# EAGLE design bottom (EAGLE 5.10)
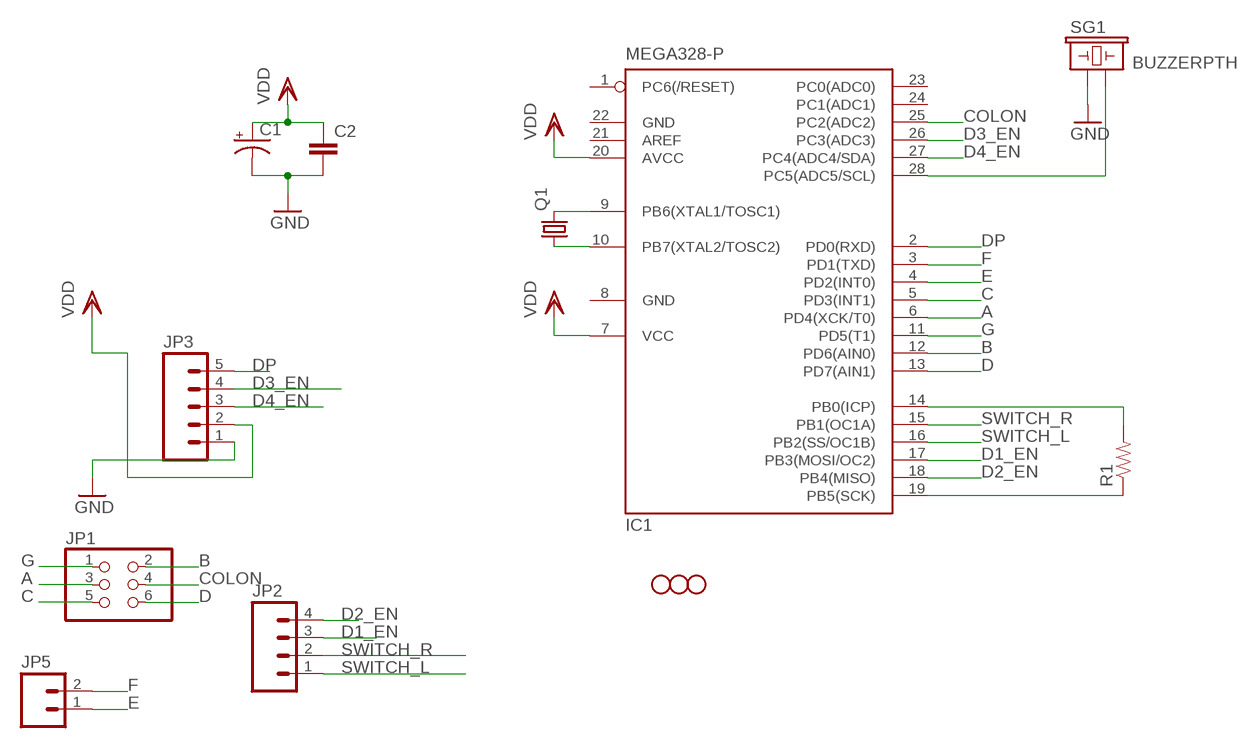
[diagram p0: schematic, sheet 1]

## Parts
C1  CAP_POLPTH2  [CPOL-RADIAL-10UF-25V]
C2  CAPPTH  [CAP-PTH-SMALL]
IC1  MEGA328-P  MEGA8-P  [DIL28-3]
JP1  PINHD-2X3  [2X03]
JP2  M04PTH  [1X04]
JP3  M05PTH  [1X05]
JP4  STAND-OFF  [STAND-OFF]
JP5  M02PTH  [1X02]
JP6  STAND-OFF  [STAND-OFF]
JP7  STAND-OFF  [STAND-OFF]
Q1  CRYSTALTC26H  [TC26H]
R1  RESISTORPTH-1/6W  [1/6W-RES]
SG1  BUZZERPTH  [BUZZER-12MM]

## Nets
A: IC1.6(PD4(XCK/T0)) JP1.3
B: IC1.12(PD6(AIN0)) JP1.2
C: IC1.5(PD3(INT1)) JP1.5
CAP_REC: IC1.19(PB5(SCK)) R1.1
CAP_TRANS: IC1.14(PB0(ICP)) R1.2
COLON: IC1.25(PC2(ADC2)) JP1.4
D: IC1.13(PD7(AIN1)) JP1.6
D1_EN: IC1.17(PB3(MOSI/OC2)) JP2.3
D2_EN: IC1.18(PB4(MISO)) JP2.4
D3_EN: IC1.26(PC3(ADC3)) JP3.4
D4_EN: IC1.27(PC4(ADC4/SDA)) JP3.3
DP: IC1.2(PD0(RXD)) JP3.5
E: IC1.4(PD2(INT0)) JP5.1
F: IC1.3(PD1(TXD)) JP5.2
G: IC1.11(PD5(T1)) JP1.1
GND: C1.2(-) C2.2 JP3.1 SG1.+
N$1: IC1.9(PB6(XTAL1/TOSC1)) Q1.2
N$2: IC1.10(PB7(XTAL2/TOSC2)) Q1.1
N$4: IC1.28(PC5(ADC5/SCL)) SG1.-
SWITCH_L: IC1.16(PB2(SS/OC1B)) JP2.1
SWITCH_R: IC1.15(PB1(OC1A)) JP2.2
VDD: C1.1(+) C2.1 IC1.7(VCC) IC1.20(AVCC) JP3.2
Unconnected: IC1.1(PC6(/RESET)) IC1.21(AREF) IC1.23(PC0(ADC0)) IC1.24(PC1(ADC1))

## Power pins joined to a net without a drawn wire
GND: IC1.8(GND) IC1.22(GND)

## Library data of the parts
C1 = SparkFun:CAP_POL: Capacitor Polarized
C2 = SparkFun:CAP: Capacitor
IC1 = atmel:MEGA8-P: MICROCONTROLLER 8 Kbytes FLASH, 1 kbytes SRAM, 512 bytes EEPROM, USART, 4-channel 10 bit ADC, 2-channel 8 bit ADC Pin compatible with Atmega48, ATMega88, ATMega168 Source: avr.lbr
JP1 = SparkFun:PINHD-2X3: PIN HEADER
JP2 = SparkFun:M04: Header 4 Standard 4-pin 0.1" header. Use with straight break away headers (SKU : PRT-00116), right angle break away headers (PRT-00553), swiss pins (PRT-00743), machine pins (PRT-00117), and female headers (PRT-00115). Molex polarized connector foot print use with SKU : PRT-08231 with associated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
JP3 = SparkFun:M05: Header 5 Standard 5-pin 0.1" header. Use with straight break away headers (SKU : PRT-00116), right angle break away headers (PRT-00553), swiss pins (PRT-00743), machine pins (PRT-00117), and female headers (PRT-00115). Molex polarized connector foot print use with SKU : PRT-08230 with associated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
JP4 JP6 JP7 = SparkFun:STAND-OFF: Stand Off
JP5 = SparkFun:M02: Header 2
Q1 = SparkFun:CRYSTAL: Crystals
R1 = SparkFun:RESISTOR: Resistor
SG1 = SparkFun:BUZZER: Buzzer 12mm

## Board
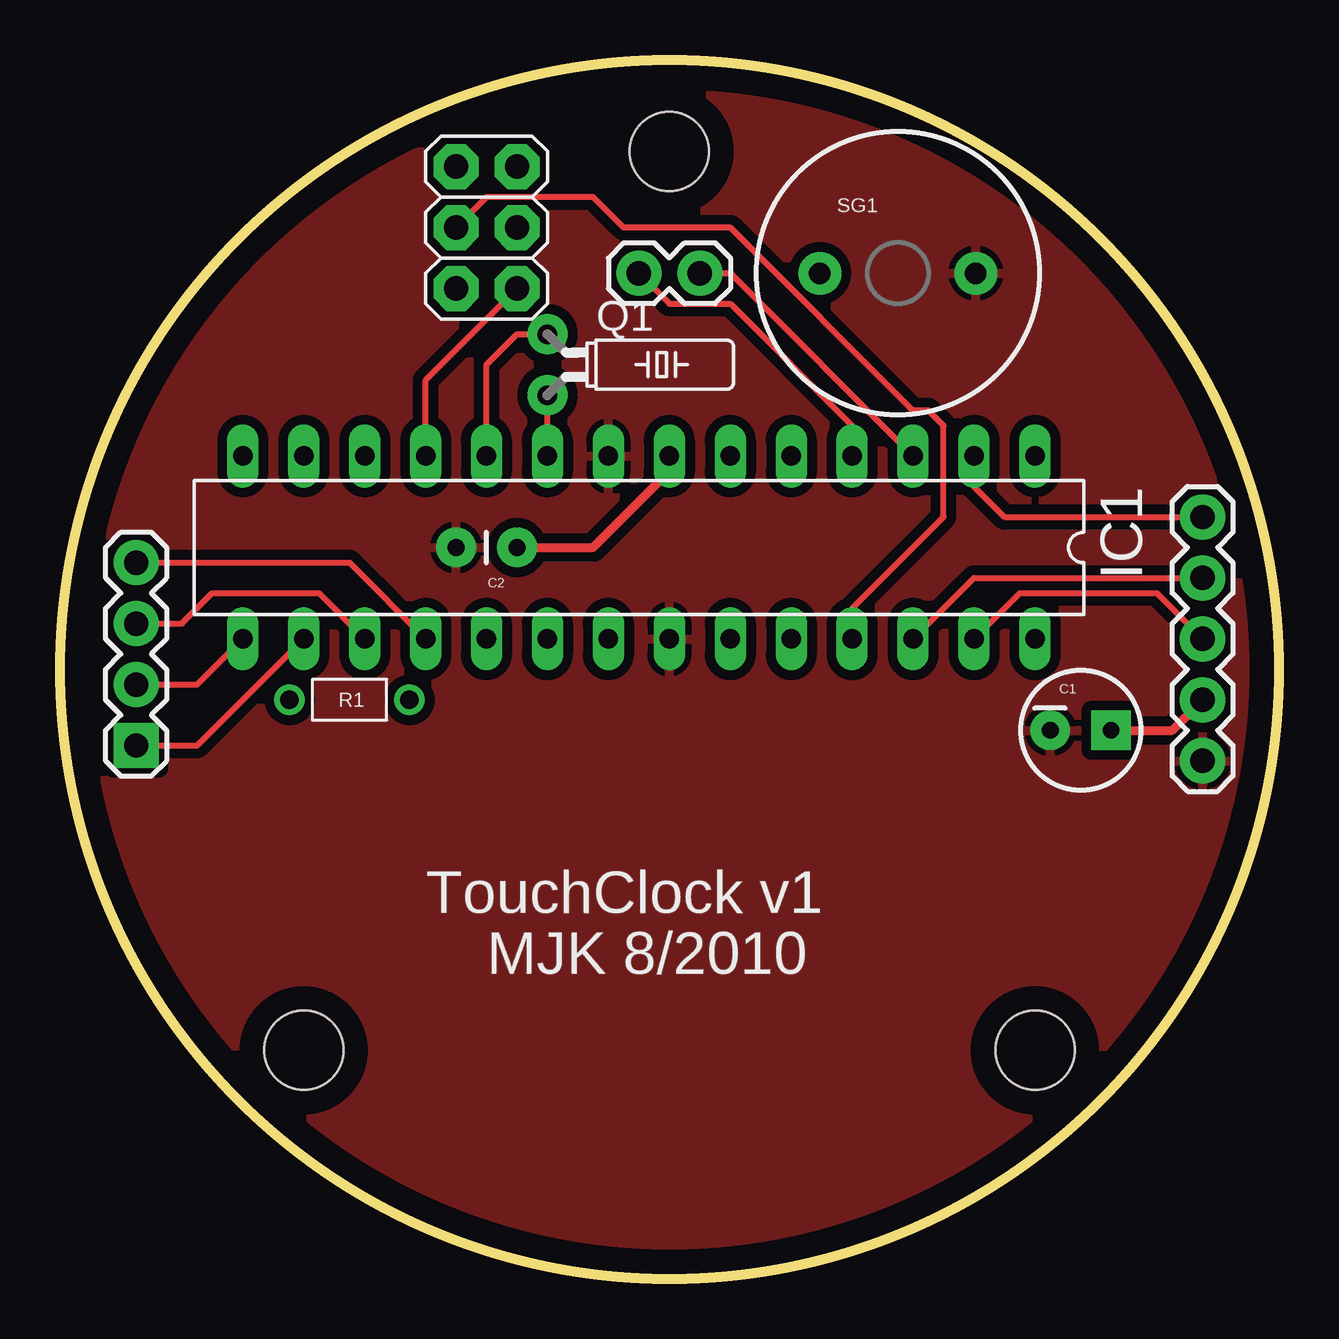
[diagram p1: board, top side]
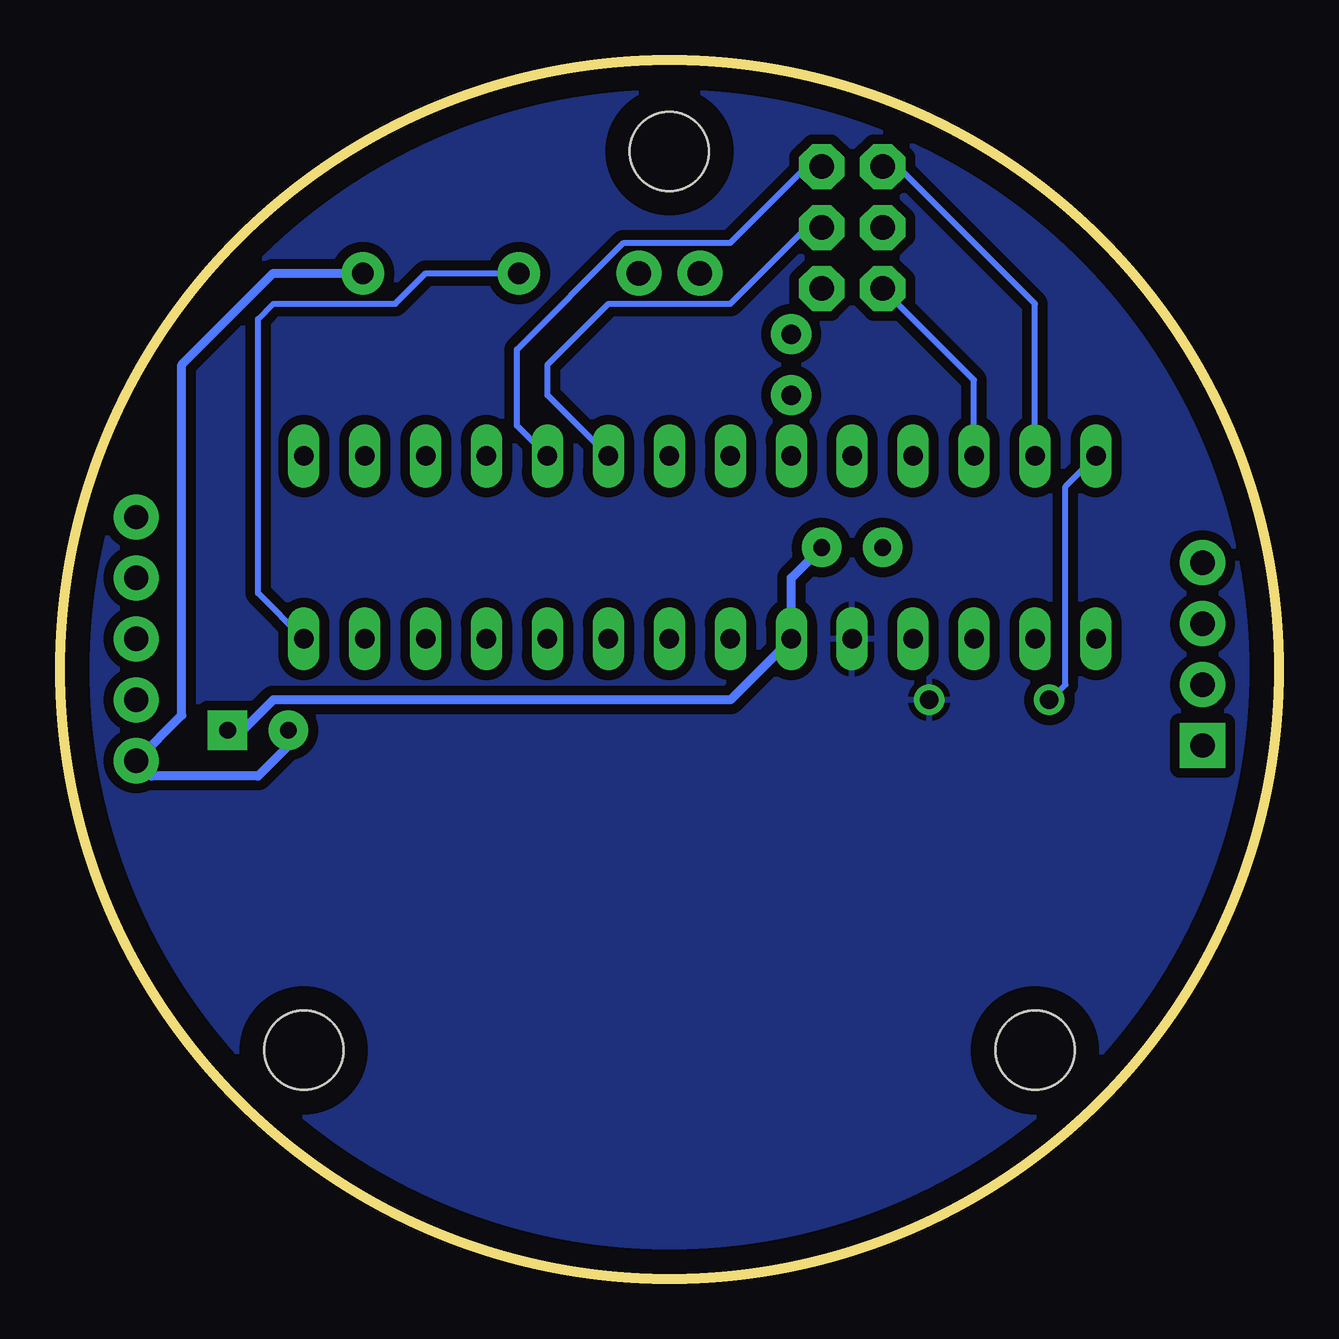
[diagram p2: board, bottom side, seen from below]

Size 50.8 x 50.8 mm. Coordinates in mm from the lower left corner, seen from the top.
Outline: circle at 25.4,25.4 radius 25.4
Copper layers (1*16): Top 0.035mm / dielectric 1.5mm / Bottom 0.035mm
Design rules "default": minimum track width 10mil, minimum drill 24mil, track to track 8mil, track to pad 8mil, pad to pad 8mil, via to via 8mil, smd to smd 8mil, copper to edge 40mil, drill to drill 8mil, minimum pad ring 10mil, minimum via ring 8mil, stop-mask expansion 4mil, vias tented up to drill 0mil, thermal gap 10mil

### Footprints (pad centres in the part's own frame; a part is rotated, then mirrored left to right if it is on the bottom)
CPOL-RADIAL-10UF-25V = drill 0.7 pad 1.651 square: 1 1.27,0 | drill 0.7 pad 1.651 round: 2 -1.27,0
CAP-PTH-SMALL = drill 0.7 pad 1.651 round: 1 0,0; 2 2.54,0
DIL28-3 = drill 0.813 long: 1 -16.51,-3.81; 2 -13.97,-3.81; 3 -11.43,-3.81; 4 -8.89,-3.81; 5 -6.35,-3.81; 6 -3.81,-3.81; 7 -1.27,-3.81; 8 1.27,-3.81; 9 3.81,-3.81; 10 6.35,-3.81; 11 8.89,-3.81; 12 11.43,-3.81; 13 13.97,-3.81; 14 16.51,-3.81; 15 16.51,3.81; 16 13.97,3.81; 17 11.43,3.81; 18 8.89,3.81; 19 6.35,3.81; 20 3.81,3.81; 21 1.27,3.81; 22 -1.27,3.81; 23 -3.81,3.81; 24 -6.35,3.81; 25 -8.89,3.81; 26 -11.43,3.81; 27 -13.97,3.81; 28 -16.51,3.81
2X03 = drill 1.016 pad 1.88 octagon: 1 -2.54,-1.27; 2 -2.54,1.27; 3 0,-1.27; 4 0,1.27; 5 2.54,-1.27; 6 2.54,1.27
1X04 = drill 1.016 pad 1.88 square: 1 0,0 | drill 1.016 pad 1.88 round: 2 2.54,0; 3 5.08,0; 4 7.62,0
1X05 = drill 1.016 pad 1.88 round: 1 0,0; 2 2.54,0; 3 5.08,0; 4 7.62,0; 5 10.16,0
STAND-OFF = hole 3.302: 0,0
1X02 = drill 1.016 pad 1.88 round: 1 0,0; 2 2.54,0
TC26H = drill 0.813 pad 1.676 round: 1 -1.27,0; 2 1.27,0
1/6W-RES = drill 0.762 round: 1 -2.5,0; 2 2.5,0
BUZZER-12MM = drill 0.9 pad 1.778 round: + 3.25,0; - -3.25,0

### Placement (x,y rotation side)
C1  42.55,22.86 0 top
C2  19.05,30.48 180 top
IC1  24.13,30.48 180 top
JP1  17.78,43.81 90 top
JP2  3.17,22.23 90 top
JP3  47.62,21.59 90 top
JP4  25.4,46.99 0 top
JP5  24.13,41.91 0 top
JP6  10.16,9.53 0 top
JP7  40.64,9.53 0 top
Q1  20.32,38.1 270 top
R1  12.06,24.13 180 top
SG1  34.92,41.91 0 top

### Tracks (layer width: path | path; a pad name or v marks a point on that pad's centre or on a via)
A
  Bottom 0.254: JP1.3 19.68,43.81 22.86,40.64 27.94,40.64 30.48,38.1 30.48,36.83 IC1.6
B
  Bottom 0.254: IC1.12 12.7,37.47 JP1.2
C
  Bottom 0.254: JP1.5 19.68,46.35 22.86,43.18 27.3,43.18 31.75,38.73 31.75,35.56 IC1.5
CAP_REC
  pour Bottom (isolate 0.406): 1.27,25.4 arc-90 25.4,49.53 26.04,49.53 arc-90 49.53,26.04 49.53,25.4 arc-90 25.4,1.27 arc-90
CAP_TRANS
  Bottom 0.254: R1.2 9.53,24.13 8.89,24.77 8.89,33.02 IC1.14
COLON
  Top 0.254: JP1.4 17.78,45.09 22.23,45.09 23.5,43.81 27.94,43.81 35.56,36.2 36.2,36.2 36.83,35.56 36.83,31.75 33.02,27.94 IC1.25
D
  Bottom 0.254: JP1.6 15.88,46.35 10.16,40.64 IC1.13
D1_EN
  Top 0.254: JP2.3 5.08,27.3 6.35,28.57 10.79,28.57 IC1.17
D2_EN
  Top 0.254: JP2.4 12.06,29.84 IC1.18
D3_EN
  Top 0.254: IC1.26 38.1,29.21 JP3.4
D4_EN
  Top 0.254: IC1.27 40.01,28.57 45.72,28.57 JP3.3
DP
  Top 0.254: IC1.2 38.1,33.02 39.37,31.75 JP3.5
  Bottom 0.254: JP3.5 47.59,31.75
E
  Top 0.254: IC1.4 33.02,35.56 27.94,40.64 25.4,40.64 JP5.1
F
  Top 0.254: JP5.2 27.94,41.91 IC1.3
G
  Top 0.254: IC1.11 15.24,37.47 JP1.1
GND
  Bottom 0.381: C1.2 41.27,22.23 42.55,20.95 46.99,20.95 JP3.1 45.72,23.5 45.72,38.1 41.91,41.91 SG1.+
  pour Top (isolate 0.406): 25.4,49.53 arc-90 49.53,25.4 arc-90 25.4,1.27 arc-90 1.27,25.4 arc-90
N$1
  Top 0.254: IC1.9 Q1.2
N$2
  Top 0.254: Q1.1 19.05,39.37 17.78,38.1 IC1.10
N$4
  Bottom 0.254: SG1.- 35.56,41.91 36.83,40.64 41.91,40.64 42.55,40.01 42.55,28.57 IC1.28
SWITCH_L
  Top 0.254: JP2.1 5.71,22.23 IC1.16
SWITCH_R
  Top 0.254: JP2.2 5.71,24.77 IC1.15
VDD
  Top 0.381: C1.1 46.35,22.86 JP3.2 | IC1.7 25.4,33.66 22.23,30.48 C2.1
  Bottom 0.381: C1.1 43.18,22.86 41.91,24.13 22.86,24.13 IC1.20 20.32,29.21 C2.1

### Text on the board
tNames: TouchClock v1 | MJK 8/2010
